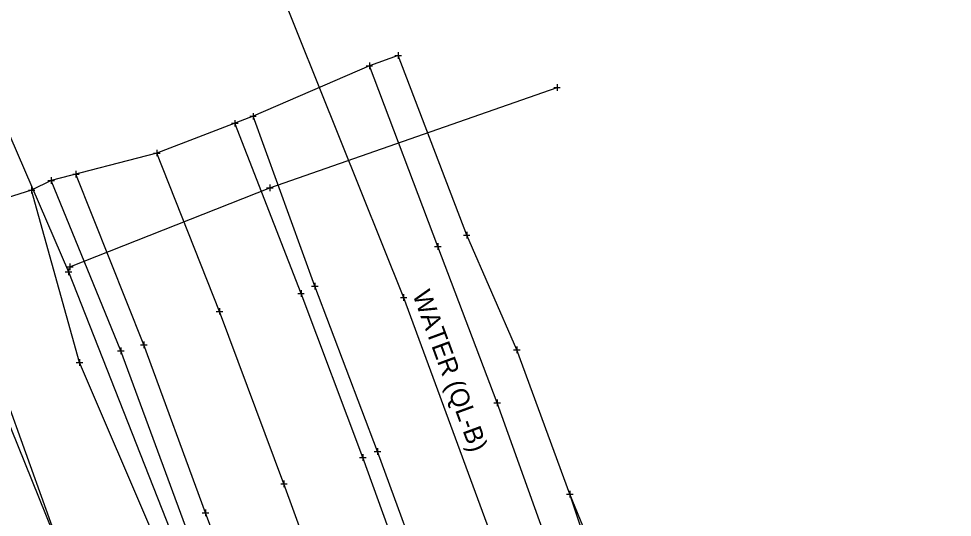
# Model space of a CAD drawing. Extents: x 2324380 to 2325559, y 691096 to 693386.
# Drawn here: x 2324992.8 to 2325134.6, y 692274.6 to 692350.4 of the extents above; entities that cross this region are included whole.
import ezdxf

# ---------------------------------------------------------------- set-up
doc = ezdxf.new("R2010")
doc.units = 0
for name, color, linetype in [('PM_X_CL_Double_Solid', 7, 'Continuous'), ('PM_X_Transverse_Line', 7, 'Continuous'), ('PV_X_COP', 7, 'Continuous'), ('PV_X_EOP', 7, 'Continuous'), ('PV_X_Walk', 7, 'Continuous'), ('SV_X_Shot_Marker', 7, 'Continuous'), ('SV_X_Terrain_Boundary', 7, 'Continuous'), ('SV_X_Toe_of_Slope', 7, 'Continuous'), ('SV_X_Top_of_Bank', 7, 'Continuous'), ('UT_X_Gas', 7, 'Continuous'), ('UT_X_Water', 7, 'Continuous'), ('UT_X_Water_Text', 7, 'Continuous')]:
    doc.layers.add(name, color=color, linetype=linetype)

msp = doc.modelspace()

# ---------------------------------------------------------------- linework, layer by layer
at = {"layer": 'PM_X_CL_Double_Solid'}
msp.add_lwpolyline([(2325089.48, 692110.68), (2325084.32, 692128.51), (2325075.39, 692156.76), (2325066.63, 692183.78), (2325058.11, 692209.28), (2325049.62, 692233.9), (2325041.55, 692256.48), (2325033.1, 692279.67), (2325023.32, 692305.87), (2325013.77, 692329.93)], dxfattribs=at)
at = {"layer": 'PM_X_Transverse_Line'}
for points in [[(2325119.99, 692049.57), (2325112.24, 692077.64), (2325103.35, 692107.53), (2325096.49, 692131.33), (2325087.35, 692159.17), (2325078.82, 692186.21), (2325070.07, 692212.52), (2325061.8, 692237.43), (2325045.09, 692283.67), (2325035.69, 692308.59), (2325025.65, 692334.45)], [(2325067.54, 692138.56), (2325063.39, 692152.82), (2325054.73, 692179.69), (2325046.66, 692204.76), (2325037.56, 692230.19), (2325029.78, 692252.06), (2325021.19, 692275.25), (2325011.82, 692300.8), (2325001.5, 692326.71)]]:
    msp.add_lwpolyline(points, dxfattribs=at)
at = {"layer": 'PV_X_COP'}
msp.add_lwpolyline([(2325108.45, 692046.03), (2325099.34, 692075.66), (2325091, 692105.35), (2325084.32, 692128.51), (2325075.39, 692156.76), (2325066.63, 692183.78), (2325058.11, 692209.28), (2325049.62, 692233.9), (2325041.55, 692256.48), (2325033.1, 692279.67), (2325023.32, 692305.87), (2325013.77, 692329.93)], dxfattribs=at)
at = {"layer": 'PV_X_EOP'}
for p, q in [((2325008.31, 692299.88), (2324997.75, 692325.76)), ((2325018.15, 692273.21), (2325008.31, 692299.88))]:
    msp.add_line(p, q, dxfattribs=at)
msp.add_lwpolyline([(2325123.25, 692051.46), (2325115.82, 692078.51), (2325110.86, 692095.71), (2325106.46, 692109.57), (2325099.73, 692132.13), (2325090.5, 692160.58), (2325082.22, 692186.84), (2325072.77, 692213.83), (2325064.19, 692238.4), (2325059.92, 692251), (2325055.34, 692262.57), (2325047.32, 692284.59), (2325037.78, 692309.71), (2325028.4, 692335.51)], dxfattribs=at)
at = {"layer": 'PV_X_Walk'}
for points in [[(2325090.6, 692235.9), (2325076.53, 692278.08), (2325068.46, 692300.04), (2325060.86, 692317.44), (2325050.46, 692344.77)], [(2325085.26, 692235.48), (2325073.57, 692269.38), (2325065.48, 692291.96), (2325056.49, 692315.71), (2325046.07, 692343.18)]]:
    msp.add_lwpolyline(points, dxfattribs=at)
at = {"layer": 'SV_X_Shot_Marker'}
for p, q in [((2325049.96, 692344.77), (2325050.96, 692344.77)), ((2325050.46, 692345.27), (2325050.46, 692344.27)), ((2325050.46, 692344.77), (2325050.46, 692344.77)), ((2325045.57, 692343.18), (2325046.57, 692343.18)), ((2325046.07, 692343.68), (2325046.07, 692342.68)), ((2325046.07, 692343.18), (2325046.07, 692343.18)), ((2325074.58, 692340.38), (2325074.58, 692339.38)), ((2325074.08, 692339.88), (2325075.08, 692339.88)), ((2325074.58, 692339.88), (2325074.58, 692339.88)), ((2325028.4, 692336.01), (2325028.4, 692335.01)), ((2325025.15, 692334.45), (2325026.15, 692334.45)), ((2325025.65, 692334.95), (2325025.65, 692333.95)), ((2325025.65, 692334.45), (2325025.65, 692334.45)), ((2325027.9, 692335.51), (2325028.9, 692335.51)), ((2325028.4, 692335.51), (2325028.4, 692335.51)), ((2325013.77, 692330.43), (2325013.77, 692329.43)), ((2325013.77, 692330.43), (2325013.77, 692329.43)), ((2325013.27, 692329.93), (2325014.27, 692329.93)), ((2325013.27, 692329.93), (2325014.27, 692329.93)), ((2325013.77, 692329.93), (2325013.77, 692329.93)), ((2325013.77, 692329.93), (2325013.77, 692329.93)), ((2325001.5, 692327.21), (2325001.5, 692326.21)), ((2324997.25, 692325.76), (2324998.25, 692325.76)), ((2324997.75, 692326.26), (2324997.75, 692325.26)), ((2324997.75, 692325.76), (2324997.75, 692325.76)), ((2325001, 692326.71), (2325002, 692326.71)), ((2325001.5, 692326.71), (2325001.5, 692326.71)), ((2324994.77, 692324.78), (2324994.77, 692323.78)), ((2325030.46, 692324.65), (2325031.46, 692324.65)), ((2325030.96, 692325.15), (2325030.96, 692324.15)), ((2325030.96, 692324.65), (2325030.96, 692324.65)), ((2324994.27, 692324.28), (2324995.27, 692324.28)), ((2324994.77, 692324.28), (2324994.77, 692324.28)), ((2325060.36, 692317.44), (2325061.36, 692317.44)), ((2325060.86, 692317.94), (2325060.86, 692316.94)), ((2325060.86, 692317.44), (2325060.86, 692317.44)), ((2325056.49, 692316.21), (2325056.49, 692315.21)), ((2325055.99, 692315.71), (2325056.99, 692315.71)), ((2325056.49, 692315.71), (2325056.49, 692315.71)), ((2325000.58, 692313.14), (2325000.58, 692312.14)), ((2324999.88, 692311.88), (2325000.88, 692311.88)), ((2325000.08, 692312.64), (2325001.08, 692312.64)), ((2325000.38, 692312.38), (2325000.38, 692311.38)), ((2325000.38, 692311.88), (2325000.38, 692311.88)), ((2325000.58, 692312.64), (2325000.58, 692312.64)), ((2325037.78, 692310.21), (2325037.78, 692309.21)), ((2325035.69, 692309.09), (2325035.69, 692308.09)), ((2325037.28, 692309.71), (2325038.28, 692309.71)), ((2325037.78, 692309.71), (2325037.78, 692309.71)), ((2325035.19, 692308.59), (2325036.19, 692308.59)), ((2325035.69, 692308.59), (2325035.69, 692308.59)), ((2325050.78, 692307.99), (2325051.78, 692307.99)), ((2325051.28, 692308.49), (2325051.28, 692307.49)), ((2325051.28, 692307.99), (2325051.28, 692307.99)), ((2325023.32, 692306.37), (2325023.32, 692305.37)), ((2325023.32, 692306.37), (2325023.32, 692305.37)), ((2325022.82, 692305.87), (2325023.82, 692305.87)), ((2325022.82, 692305.87), (2325023.82, 692305.87)), ((2325023.32, 692305.87), (2325023.32, 692305.87)), ((2325023.32, 692305.87), (2325023.32, 692305.87)), ((2325008.31, 692300.38), (2325008.31, 692299.38)), ((2325011.32, 692300.8), (2325012.32, 692300.8)), ((2325011.82, 692301.3), (2325011.82, 692300.3)), ((2325011.82, 692300.8), (2325011.82, 692300.8)), ((2325068.46, 692300.54), (2325068.46, 692299.54)), ((2325007.81, 692299.88), (2325008.81, 692299.88)), ((2325008.31, 692299.88), (2325008.31, 692299.88)), ((2325067.96, 692300.04), (2325068.96, 692300.04)), ((2325068.46, 692300.04), (2325068.46, 692300.04)), ((2325001.53, 692298.08), (2325002.53, 692298.08)), ((2325002.03, 692298.58), (2325002.03, 692297.58)), ((2325002.03, 692298.08), (2325002.03, 692298.08)), ((2325064.98, 692291.96), (2325065.98, 692291.96)), ((2325065.48, 692292.46), (2325065.48, 692291.46)), ((2325065.48, 692291.96), (2325065.48, 692291.96)), ((2325047.32, 692285.09), (2325047.32, 692284.09)), ((2325044.59, 692283.67), (2325045.59, 692283.67)), ((2325045.09, 692284.17), (2325045.09, 692283.17)), ((2325045.09, 692283.67), (2325045.09, 692283.67)), ((2325046.82, 692284.59), (2325047.82, 692284.59)), ((2325047.32, 692284.59), (2325047.32, 692284.59)), ((2325032.6, 692279.67), (2325033.6, 692279.67)), ((2325032.6, 692279.67), (2325033.6, 692279.67)), ((2325033.1, 692280.17), (2325033.1, 692279.17)), ((2325033.1, 692280.17), (2325033.1, 692279.17)), ((2325033.1, 692279.67), (2325033.1, 692279.67)), ((2325033.1, 692279.67), (2325033.1, 692279.67)), ((2325076.03, 692278.08), (2325077.03, 692278.08)), ((2325076.53, 692278.58), (2325076.53, 692277.58)), ((2325076.53, 692278.08), (2325076.53, 692278.08)), ((2325020.69, 692275.25), (2325021.69, 692275.25)), ((2325021.19, 692275.75), (2325021.19, 692274.75)), ((2325021.19, 692275.25), (2325021.19, 692275.25))]:
    msp.add_line(p, q, dxfattribs=at)
at = {"layer": 'SV_X_Terrain_Boundary'}
msp.add_lwpolyline([(2325110.91, 692166.99), (2325109.19, 692174.04), (2325100.28, 692217.91), (2325098.88, 692222), (2325093.57, 692236.62), (2325076.53, 692278.08), (2325068.46, 692300.04), (2325060.86, 692317.44), (2325050.46, 692344.77), (2325046.07, 692343.18), (2325028.4, 692335.51), (2325013.77, 692329.93), (2324997.75, 692325.76), (2324994.77, 692324.28), (2324978.96, 692319.34), (2325000.08, 692267.16), (2325014.61, 692222.14), (2325030.56, 692121.28)], dxfattribs=at)
at = {"layer": 'SV_X_Toe_of_Slope'}
msp.add_lwpolyline([(2325030.56, 692121.28), (2325044.25, 692124.98), (2325039.46, 692146.35), (2325032.38, 692172.92), (2325024.69, 692196.66), (2325014.61, 692222.14), (2325009.37, 692243.9), (2325000.08, 692267.16), (2324990.82, 692292.96), (2324978.96, 692319.34)], dxfattribs=at)
at = {"layer": 'SV_X_Top_of_Bank'}
msp.add_lwpolyline([(2325035.08, 692109.4), (2325044.3, 692119.16), (2325050, 692123.78), (2325050.31, 692149.89), (2325046.25, 692177.76), (2325037.53, 692201.96), (2325029.65, 692226.14), (2325021.48, 692249.35), (2325013.46, 692271.39), (2325002.03, 692298.08), (2324994.77, 692324.28)], dxfattribs=at)
at = {"layer": 'UT_X_Gas'}
for points in [[(2324898.38, 692544.09), (2324919.05, 692496.67), (2324937.7, 692455), (2324959.41, 692406.62), (2324976.91, 692366.17), (2325000.38, 692311.88), (2325017.09, 692269.4), (2325035.58, 692222.9), (2325041.06, 692204.36), (2325050.14, 692178.45), (2325064.12, 692139.21), (2325054.72, 692138.03), (2325055.52, 692128.26), (2325054.24, 692120.72), (2325042.69, 692106.28), (2325010.21, 692097.08)], [(2325000.58, 692312.64), (2325030.96, 692324.65), (2325074.58, 692339.88)]]:
    msp.add_lwpolyline(points, dxfattribs=at)
at = {"layer": 'UT_X_Water'}
msp.add_lwpolyline([(2324934.92, 692571.2), (2324956.29, 692529.58), (2324976.21, 692488), (2324991.94, 692453.33), (2325012.4, 692405.82), (2325031.94, 692356.27), (2325051.28, 692307.99), (2325065.92, 692268.22), (2325079.64, 692231.2), (2325091.06, 692197.41), (2325105.98, 692152.66), (2325121.62, 692099.73), (2325124.52, 692091.67), (2325134.64, 692057.74)], dxfattribs=at)

# ---------------------------------------------------------------- texts
at = {"layer": 'UT_X_Water_Text'}
msp.add_text('WATER (QL-B)', height=2.8, rotation=290.2207, dxfattribs=at).set_placement((2325052.59, 692308.47))

doc.saveas('drawing.dxf')
